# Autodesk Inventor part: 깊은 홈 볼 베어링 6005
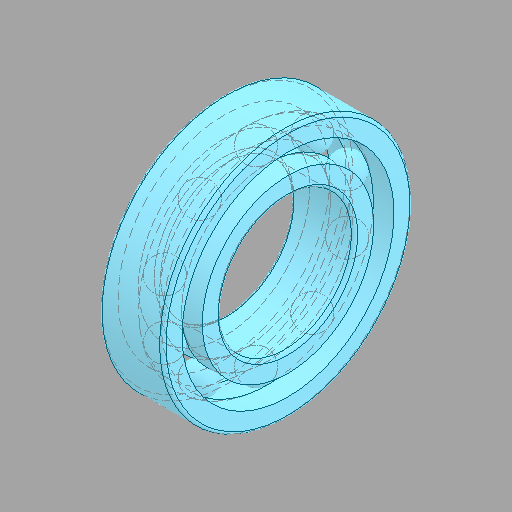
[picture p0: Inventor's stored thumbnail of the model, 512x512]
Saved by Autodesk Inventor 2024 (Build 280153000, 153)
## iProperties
Created: 2025-11
Part Number: 깊은 홈 볼 베어링 6005
Material: 강철, 연강
Description: 깊은 그루브 볼 베어링
Document SubType Name: Modeling
Designer: Edu09
Density: 7.85 g/cm^3
Appearance: 기본값
Author: jhkim
Sending System: Autodesk Inventor 2026
Preprocessor: ST-DEVELOPER v20.1
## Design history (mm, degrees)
feature "Solid1"
feature "Solid1:1"
feature "Solid1:2"
feature "Solid1:3"
feature "Solid1:4"
feature "Solid1:5"
feature "Solid1:6"
feature "Solid1:7"
feature "Solid1:8"
feature "Solid1:9"
feature "Solid1:10"
feature "Solid1:11"
node "솔리드1"
node "솔리드2"
node "솔리드3"
node "솔리드4"
node "솔리드5"
node "솔리드6"
node "솔리드7"
node "솔리드8"
node "솔리드9"
node "솔리드10"
node "솔리드11"
node "솔리드12"
